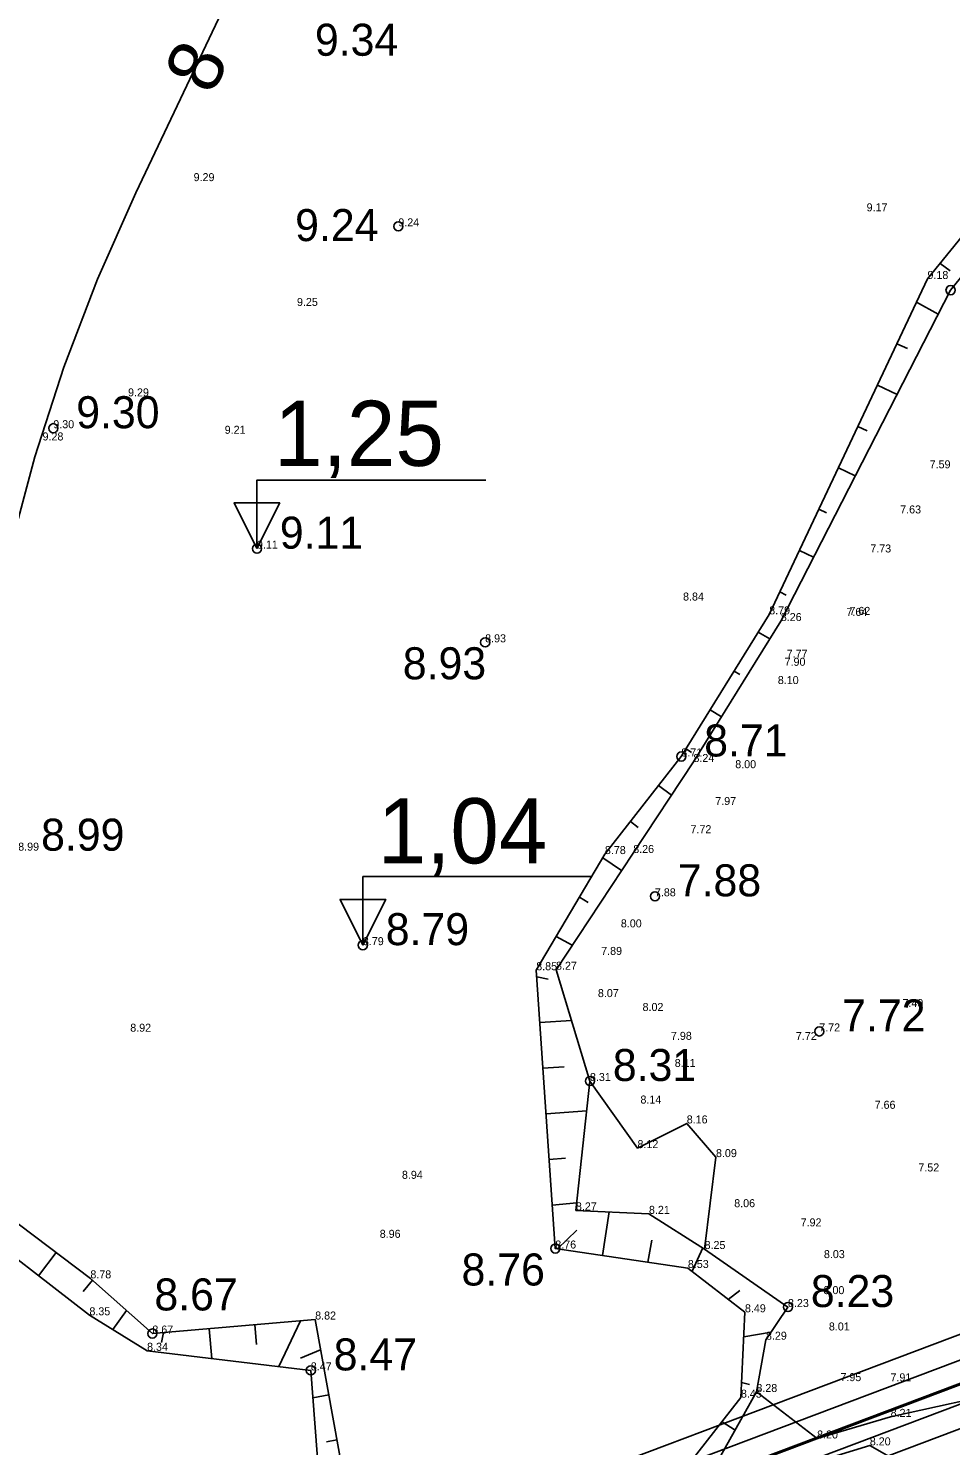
# Model space of a CAD drawing. Extents: x 433497 to 434382, y 6534486 to 6534993.
# Drawn here: x 433855.8 to 433896.1, y 6534702.9 to 6534764.8 of the extents above; entities that cross this region are included whole.
import ezdxf

# ---------------------------------------------------------------- set-up
doc = ezdxf.new("R2010")
doc.units = 0
for name, color, linetype in [('Default', 7, 'Continuous'), ('jääkpaksus', 7, 'Continuous'), ('kataster', 7, 'Continuous'), ('KORGUS-EH2000', 7, 'Continuous'), ('Lamami horisontaal', 7, 'Continuous'), ('MOOTKORG-EH2000', 7, 'Continuous'), ('PIIR', 7, 'Continuous'), ('RELJEEF', 7, 'Continuous'), ('VEEKOGU', 7, 'Continuous')]:
    doc.layers.add(name, color=color, linetype=linetype)

msp = doc.modelspace()

# ---------------------------------------------------------------- linework, layer by layer
at = {"layer": 'Default'}
msp.add_lwpolyline([(433617.12, 6534791.025), (433632.75, 6534606.045), (434137.38, 6534796.515), (434127.69, 6534855.6), (433968.21, 6534911.925), (433942.38, 6534904.035), (433920.99, 6534907.275)], close=True, dxfattribs=at)
msp.add_lwpolyline([(433617.12, 6534791.025), (433632.75, 6534606.045), (434137.38, 6534796.515), (434127.69, 6534855.6), (433968.21, 6534911.925), (433942.38, 6534904.035), (433920.99, 6534907.275)], close=True, dxfattribs=at)
msp.add_lwpolyline([(433617.12, 6534791.025), (433632.75, 6534606.045), (434137.38, 6534796.515), (434127.69, 6534855.6), (433968.21, 6534911.925), (433942.38, 6534904.035), (433920.99, 6534907.275)], close=True, dxfattribs=at)
at = {"layer": 'jääkpaksus'}
for points in [[(433865.749, 6534742.069), (433865.749, 6534745.069), (433875.749, 6534745.069)], [(433870.38, 6534724.733), (433870.38, 6534727.733), (433880.38, 6534727.733)]]:
    msp.add_lwpolyline(points, dxfattribs=at)
for points in [[(433865.749, 6534742.069), (433864.749, 6534744.069), (433866.749, 6534744.069)], [(433870.38, 6534724.733), (433869.38, 6534726.733), (433871.38, 6534726.733)]]:
    msp.add_lwpolyline(points, close=True, dxfattribs=at)
at = {"layer": 'kataster'}
msp.add_lwpolyline([(433617.102, 6534791.002), (433632.769, 6534606.029), (434137.446, 6534796.469), (434127.827, 6534855.589), (433950.026, 6534918.39)], close=True, dxfattribs=at)
at = {"layer": 'KORGUS-EH2000'}
for centre in [(433871.93, 6534756.161), (433896.07, 6534753.37), (433856.848, 6534747.334), (433865.749, 6534742.069), (433875.726, 6534737.973), (433884.3, 6534732.983), (433883.146, 6534726.868), (433870.38, 6534724.733), (433890.33, 6534720.961), (433880.307, 6534718.793), (433878.791, 6534711.468), (433888.963, 6534708.91), (433861.177, 6534707.751), (433868.104, 6534706.14)]:
    msp.add_circle(centre, 0.2, dxfattribs=at)
at = {"layer": 'Lamami horisontaal'}
msp.add_lwpolyline([(433843.243, 6534685.427), (433843.19, 6534685.542), (433843.091, 6534685.772), (433842.997, 6534686.004), (433842.379, 6534687.584), (433842.273, 6534687.927), (433842.221, 6534688.273), (433842.224, 6534688.624), (433842.282, 6534688.978), (433854.971, 6534742.091), (433856.035, 6534746.082), (433857.302, 6534750), (433858.774, 6534753.846), (433860.448, 6534757.621), (433867.555, 6534772.575)], dxfattribs=at)
at = {"layer": 'PIIR'}
for points in [[(433632.021, 6534604.835), (434138.248, 6534795.936), (434128.468, 6534856.135), (433968.226, 6534912.818), (433942.33, 6534904.85), (433920.952, 6534908.165), (433616.327, 6534791.524), (433632.021, 6534604.835)], [(433632.732, 6534605.959), (434137.353, 6534796.454), (434127.754, 6534855.539), (433968.208, 6534911.976), (433942.39, 6534904.031), (433921.04, 6534907.341), (433617.174, 6534790.992), (433632.732, 6534605.959)], [(433633.446, 6534604.304), (434134.891, 6534793.6)]]:
    msp.add_lwpolyline(points, dxfattribs=at)
for points in [[(433618.234, 6534790.327), (433921.149, 6534906.313), (433942.464, 6534903.008), (433968.187, 6534910.923), (434126.862, 6534854.794), (434136.235, 6534797.101), (433633.617, 6534607.362)], [(433619.24, 6534789.695), (433634.52, 6534608.851), (434135.141, 6534797.808), (434125.908, 6534854.108), (433968.165, 6534909.82), (433942.53, 6534901.99), (433921.212, 6534905.219)], [(433619.24, 6534789.695), (433634.52, 6534608.851), (434135.141, 6534797.808), (434125.908, 6534854.108), (433968.165, 6534909.82), (433942.53, 6534901.99), (433921.212, 6534905.219)]]:
    msp.add_lwpolyline(points, close=True, dxfattribs=at)
at = {"layer": 'RELJEEF'}
for p, q in [((433896.058, 6534754.221), (433895.611, 6534754.536)), ((433894.58, 6534752.839), (433895.534, 6534752.326)), ((433894.187, 6534750.813), (433893.726, 6534751.03)), ((433892.873, 6534749.221), (433893.733, 6534748.815)), ((433892.42, 6534747.224), (433892.02, 6534747.412)), ((433891.166, 6534745.604), (433891.907, 6534745.254)), ((433890.653, 6534743.634), (433890.313, 6534743.795)), ((433889.46, 6534741.986), (433890.08, 6534741.693)), ((433888.883, 6534740.038), (433888.606, 6534740.177)), ((433887.662, 6534738.418), (433888.167, 6534738.126)), ((433886.857, 6534736.564), (433886.61, 6534736.717)), ((433885.558, 6534735.016), (433886.05, 6534734.711)), ((433884.744, 6534733.152), (433884.506, 6534733.315)), ((433883.308, 6534731.716), (433883.868, 6534731.287)), ((433882.418, 6534729.876), (433882.076, 6534730.141)), ((433880.863, 6534728.552), (433881.69, 6534727.994)), ((433880.232, 6534726.602), (433879.845, 6534726.83)), ((433878.827, 6534725.108), (433879.533, 6534724.731)), ((433878.478, 6534723.251), (433877.978, 6534723.347)), ((433878.114, 6534721.352), (433879.498, 6534721.446)), ((433879.174, 6534719.419), (433878.251, 6534719.356)), ((433878.388, 6534717.361), (433880.165, 6534717.483)), ((433879.235, 6534715.414), (433878.524, 6534715.366)), ((433878.661, 6534713.37), (433879.729, 6534713.469)), ((433880.862, 6534711.164), (433881.142, 6534713.067)), ((433879.728, 6534712.274), (433878.883, 6534711.454)), ((433883.011, 6534711.836), (433882.841, 6534710.873)), ((433856.968, 6534711.294), (433856.2, 6534710.28)), ((433884.773, 6534710.473), (433885.243, 6534711.494)), ((433858.148, 6534709.585), (433858.559, 6534710.084)), ((433886.86, 6534709.634), (433886.353, 6534709.247)), ((433860.052, 6534708.753), (433859.444, 6534707.922)), ((433861.571, 6534707.364), (433861.669, 6534707.793)), ((433863.661, 6534707.965), (433863.774, 6534706.658)), ((433865.728, 6534707.276), (433865.654, 6534708.137)), ((433867.647, 6534708.309), (433866.71, 6534706.307)), ((433887.031, 6534707.606), (433888.224, 6534707.813)), ((433867.648, 6534706.669), (433868.534, 6534707.037)), ((433887.281, 6534705.518), (433886.937, 6534705.608)), ((433868.889, 6534705.069), (433868.194, 6534704.944)), ((433886.079, 6534703.894), (433886.651, 6534703.532)), ((433868.794, 6534703.02), (433869.244, 6534703.101))]:
    msp.add_line(p, q, dxfattribs=at)
for points in [[(433836.51, 6534724.993), (433839.722, 6534730.314), (433843.112, 6534725.867), (433850.656, 6534716.817), (433853.509, 6534713.897), (433858.468, 6534710.165), (433861.177, 6534707.751), (433868.295, 6534708.365), (433869.862, 6534699.668), (433872.606, 6534698.155), (433880.692, 6534699.223), (433884.244, 6534701.553), (433886.906, 6534704.949), (433887.082, 6534708.682), (433884.587, 6534710.617), (433878.791, 6534711.468), (433877.958, 6534723.638), (433880.96, 6534728.715), (433884.3, 6534732.983), (433888.143, 6534739.195), (433895.061, 6534753.859), (433899.33, 6534759.117), (433904.949, 6534763.914), (433915.987, 6534768.78)], [(433916.484, 6534767.586), (433905.134, 6534762.547), (433900.139, 6534758.389), (433896.07, 6534753.37), (433888.649, 6534738.904), (433884.83, 6534732.743), (433882.198, 6534728.762), (433878.824, 6534723.659), (433880.307, 6534718.793), (433879.693, 6534713.136), (433882.886, 6534712.985), (433885.317, 6534711.447), (433888.963, 6534708.91), (433888.001, 6534707.482), (433887.582, 6534705.196), (433885.049, 6534700.668), (433881.086, 6534698.719), (433871.506, 6534696.924), (433869.679, 6534698.635), (433868.465, 6534701.335), (433868.104, 6534706.14), (433860.946, 6534706.997), (433858.426, 6534708.55), (433852.899, 6534712.846)], [(433885.317, 6534711.447), (433885.816, 6534715.466), (433884.538, 6534716.938), (433882.385, 6534715.859), (433880.307, 6534718.793)], [(433887.582, 6534705.196), (433890.236, 6534703.163), (433893.451, 6534704.108), (433898.883, 6534705.309), (433914.68, 6534711.923), (433920.793, 6534714.007)]]:
    msp.add_lwpolyline(points, dxfattribs=at)
at = {"layer": 'VEEKOGU'}
for points in [[(433871.506, 6534696.924), (433881.086, 6534698.719), (433885.049, 6534700.668), (433887.582, 6534705.196), (433888.001, 6534707.482), (433888.963, 6534708.91), (433885.317, 6534711.447), (433882.886, 6534712.985), (433879.693, 6534713.136), (433880.307, 6534718.793), (433878.824, 6534723.659), (433882.198, 6534728.762), (433884.83, 6534732.743), (433888.649, 6534738.904), (433896.07, 6534753.37), (433900.139, 6534758.389), (433905.134, 6534762.547), (433916.484, 6534767.586)], [(433916.484, 6534767.586), (433905.134, 6534762.547), (433900.139, 6534758.389), (433896.07, 6534753.37), (433888.649, 6534738.904), (433884.83, 6534732.743), (433882.198, 6534728.762), (433878.824, 6534723.659), (433880.307, 6534718.793), (433879.693, 6534713.136), (433882.886, 6534712.985), (433885.317, 6534711.447), (433888.963, 6534708.91), (433888.001, 6534707.482), (433887.582, 6534705.196), (433885.049, 6534700.668)], [(433925.672, 6534711.253), (433923.536, 6534710.303), (433917.119, 6534707.774), (433903.078, 6534702.488), (433898.531, 6534700.346), (433895.329, 6534701.275), (433892.54, 6534702.862), (433885.584, 6534700.735), (433885.049, 6534700.668)]]:
    msp.add_lwpolyline(points, dxfattribs=at)

# ---------------------------------------------------------------- texts
at = {"layer": 'jääkpaksus'}
for s, p in [('1,25', (433866.502, 6534745.686)), (' 1,04', (433869.968, 6534728.308))]:
    msp.add_text(s, height=2.85, rotation=360, dxfattribs=at).set_placement(p)
at = {"layer": 'KORGUS-EH2000'}
for s, p in [('9.34', (433868.283, 6534763.62)), ('9.24', (433867.418, 6534755.516)), ('9.30', (433857.848, 6534747.334)), ('9.11', (433866.749, 6534742.069)), ('8.93', (433872.125, 6534736.357)), ('8.71', (433885.3, 6534732.983)), ('8.99', (433856.313, 6534728.864)), ('7.88', (433884.146, 6534726.868)), ('8.79', (433871.38, 6534724.733)), ('7.72', (433891.33, 6534720.961)), ('8.31', (433881.307, 6534718.793)), ('8.76', (433874.693, 6534709.852)), ('8.23', (433889.963, 6534708.91)), ('8.67', (433861.265, 6534708.762)), ('8.47', (433869.104, 6534706.14))]:
    msp.add_text(s, height=1.4, dxfattribs=at).set_placement(p)
at = {"layer": 'Lamami horisontaal'}
msp.add_text('8', height=2.4, rotation=64.58138, dxfattribs=at).set_placement((433863.784, 6534761.844))
at = {"layer": 'MOOTKORG-EH2000'}
for s, p in [('9.29', (433862.981, 6534758.138)), ('9.17', (433892.401, 6534756.817)), ('9.24', (433871.93, 6534756.161)), ('9.18', (433895.061, 6534753.859)), ('9.25', (433867.499, 6534752.68)), ('9.29', (433860.115, 6534748.727)), ('9.30', (433856.848, 6534747.334)), ('9.28', (433856.377, 6534746.8)), ('9.21', (433864.339, 6534747.092)), ('7.59', (433895.157, 6534745.582)), ('7.63', (433893.869, 6534743.609)), ('9.11', (433865.749, 6534742.069)), ('9.11', (433865.749, 6534742.069)), ('7.73', (433892.562, 6534741.902)), ('8.84', (433884.376, 6534739.8)), ('8.79', (433888.143, 6534739.195)), ('7.64', (433891.517, 6534739.128)), ('7.62', (433891.649, 6534739.173)), ('8.26', (433888.649, 6534738.904)), ('8.93', (433875.726, 6534737.973)), ('7.77', (433888.907, 6534737.303)), ('7.90', (433888.815, 6534736.948)), ('8.10', (433888.519, 6534736.149)), ('8.71', (433884.3, 6534732.983)), ('8.24', (433884.83, 6534732.743)), ('8.00', (433886.658, 6534732.47)), ('7.97', (433885.785, 6534730.86)), ('7.72', (433884.702, 6534729.628)), ('8.99', (433855.313, 6534728.864)), ('8.78', (433880.96, 6534728.715)), ('8.26', (433882.198, 6534728.762)), ('7.88', (433883.146, 6534726.868)), ('8.00', (433881.657, 6534725.51)), ('8.79', (433870.38, 6534724.733)), ('8.79', (433870.38, 6534724.733)), ('7.89', (433880.798, 6534724.306)), ('8.85', (433877.958, 6534723.638)), ('8.27', (433878.824, 6534723.659)), ('8.07', (433880.654, 6534722.462)), ('8.02', (433882.606, 6534721.855)), ('7.49', (433893.969, 6534722.026)), ('8.92', (433860.211, 6534720.948)), ('7.98', (433883.847, 6534720.593)), ('7.72', (433889.308, 6534720.586)), ('7.72', (433890.33, 6534720.961)), ('8.11', (433884.012, 6534719.408)), ('8.31', (433880.307, 6534718.793)), ('8.14', (433882.514, 6534717.808)), ('7.66', (433892.752, 6534717.579)), ('8.16', (433884.538, 6534716.938)), ('8.12', (433882.385, 6534715.859)), ('8.09', (433885.816, 6534715.466)), ('8.94', (433872.088, 6534714.517)), ('7.52', (433894.664, 6534714.839)), ('8.27', (433879.693, 6534713.136)), ('8.06', (433886.613, 6534713.276)), ('8.21', (433882.886, 6534712.985)), ('7.92', (433889.517, 6534712.437)), ('8.96', (433871.117, 6534711.937)), ('8.76', (433878.791, 6534711.468)), ('8.25', (433885.317, 6534711.447)), ('8.53', (433884.587, 6534710.617)), ('8.03', (433890.534, 6534711.05)), ('8.78', (433858.468, 6534710.165)), ('8.00', (433890.517, 6534709.476)), ('8.49', (433887.082, 6534708.682)), ('8.23', (433888.963, 6534708.91)), ('8.35', (433858.426, 6534708.55)), ('8.82', (433868.295, 6534708.365)), ('8.67', (433861.177, 6534707.751)), ('8.29', (433888.001, 6534707.482)), ('8.01', (433890.751, 6534707.886)), ('8.34', (433860.946, 6534706.997)), ('8.47', (433868.104, 6534706.14)), ('7.95', (433891.257, 6534705.671)), ('7.91', (433893.444, 6534705.662)), ('8.28', (433887.582, 6534705.196)), ('8.45', (433886.906, 6534704.949)), ('8.21', (433893.451, 6534704.108)), ('8.20', (433890.236, 6534703.163)), ('8.20', (433892.54, 6534702.862))]:
    msp.add_text(s, height=0.35, dxfattribs=at).set_placement(p)

doc.saveas('drawing.dxf')
